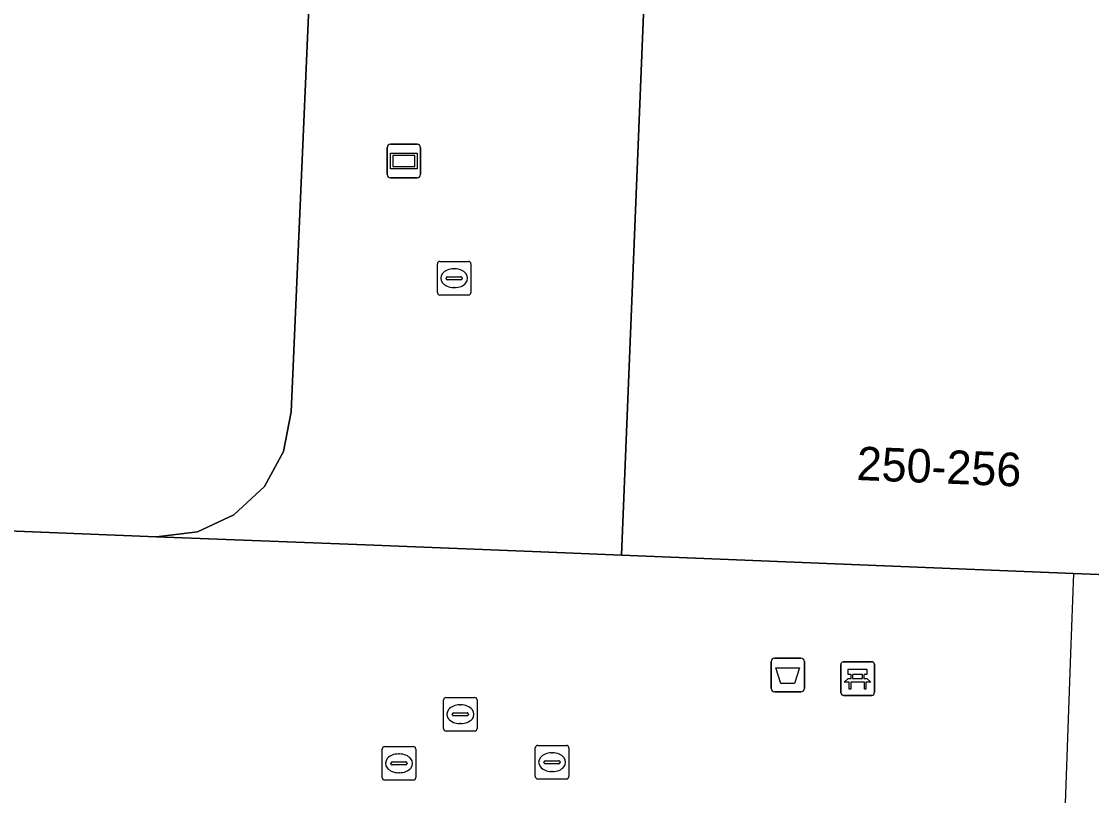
# Model space of a CAD drawing. Extents: x 160888 to 161385, y 386490 to 386908.
# Drawn here: x 161173.3 to 161205.21, y 386561.84 to 386584.91 of the extents above; entities that cross this region are included whole.
import ezdxf

# ---------------------------------------------------------------- set-up
doc = ezdxf.new("R2010")
doc.units = 0
for name, color, linetype in [('IMGEO_Afvalbak', 7, 'Continuous'), ('IMGEO_Bank', 7, 'Continuous'), ('IMGEO_Hek', 7, 'Continuous'), ('IMGEO_Kolk', 7, 'Continuous'), ('IMGEO_Pand', 7, 'Continuous'), ('IMGEO_Pand_nummerreeks', 7, 'Continuous'), ('IMGEO_Reclamebord', 7, 'Continuous'), ('IMGEO_Rioolput', 7, 'Continuous'), ('IMGEO_Voetgangersgebied_open', 7, 'Continuous')]:
    doc.layers.add(name, color=color, linetype=linetype)

msp = doc.modelspace()

# ---------------------------------------------------------------- linework, layer by layer
at = {"layer": 'IMGEO_Afvalbak'}
for p, q in [((161195.655, 386565.033), (161195.655, 386565.833)), ((161195.655, 386565.833), (161195.655, 386565.033)), ((161195.755, 386565.933), (161196.545, 386565.933)), ((161196.545, 386565.933), (161195.755, 386565.933)), ((161196.645, 386565.833), (161196.645, 386565.033)), ((161196.645, 386565.033), (161196.645, 386565.833)), ((161196.545, 386564.933), (161195.755, 386564.933)), ((161195.755, 386564.933), (161196.545, 386564.933))]:
    msp.add_line(p, q, dxfattribs=at)
msp.add_lwpolyline([(161195.798, 386565.647), (161196.502, 386565.647), (161196.353, 386565.177), (161195.947, 386565.177), (161195.798, 386565.647)], dxfattribs=at)
for centre, start, end in [((161195.755, 386565.833), 90, 180), ((161195.755, 386565.833), 90, 180), ((161196.545, 386565.833), 0, 90), ((161196.545, 386565.833), 360, 90), ((161195.755, 386565.033), 180, 270), ((161195.755, 386565.033), 180, 270), ((161196.545, 386565.033), 270, 0), ((161196.545, 386565.033), 270, 0)]:
    msp.add_arc(centre, 0.1, start, end, dxfattribs=at)
at = {"layer": 'IMGEO_Bank'}
for p, q in [((161197.732, 386564.9), (161197.732, 386565.741)), ((161197.732, 386565.741), (161197.732, 386564.9)), ((161197.807, 386565.825), (161198.648, 386565.825)), ((161198.648, 386565.825), (161197.807, 386565.825)), ((161198.732, 386565.75), (161198.732, 386564.909)), ((161198.732, 386564.909), (161198.732, 386565.75)), ((161198.041, 386565.331), (161198.041, 386565.437)), ((161198.085, 386565.437), (161198.085, 386565.331)), ((161198.373, 386565.443), (161198.091, 386565.443)), ((161198.091, 386565.325), (161198.373, 386565.325)), ((161198.379, 386565.331), (161198.379, 386565.437)), ((161198.423, 386565.437), (161198.423, 386565.331)), ((161198.429, 386565.223), (161198.036, 386565.223)), ((161198.657, 386564.825), (161197.816, 386564.825)), ((161197.816, 386564.825), (161198.657, 386564.825))]:
    msp.add_line(p, q, dxfattribs=at)
for points in [[(161197.979, 386565.223), (161197.837, 386565.223), (161197.949, 386565.325), (161198.035, 386565.325)], [(161198.035, 386565.443), (161197.949, 386565.443), (161197.949, 386565.604), (161198.512, 386565.604), (161198.512, 386565.443), (161198.429, 386565.443)], [(161198.429, 386565.325), (161198.512, 386565.325), (161198.624, 386565.223), (161198.485, 386565.223)], [(161198.029, 386565.216), (161198.029, 386565.009), (161197.986, 386565.009), (161197.986, 386565.216)], [(161198.479, 386565.216), (161198.479, 386565.009), (161198.435, 386565.009), (161198.435, 386565.216)]]:
    msp.add_lwpolyline(points, dxfattribs=at)
for centre, radius, start, end in [((161197.81, 386565.747), 0.0779, 92.4484, 184.2845), ((161197.81, 386565.747), 0.0779, 92.4484, 184.2845), ((161198.654, 386565.747), 0.0779, 2.4484, 94.2845), ((161198.654, 386565.747), 0.0779, 2.4484, 94.2845), ((161198.034, 386565.436), 0.00671, 2.8957, 87.1043), ((161198.034, 386565.332), 0.00671, 272.8957, 357.1043), ((161198.091, 386565.436), 0.00671, 92.8957, 177.1043), ((161198.091, 386565.332), 0.00671, 182.8957, 267.1043), ((161198.373, 386565.436), 0.00671, 2.8957, 87.1043), ((161198.373, 386565.332), 0.00671, 272.8957, 357.1043), ((161198.43, 386565.436), 0.00671, 92.8957, 177.1043), ((161198.43, 386565.332), 0.00671, 182.8957, 267.1043), ((161197.979, 386565.216), 0.00671, 2.8957, 87.1043), ((161198.036, 386565.216), 0.00671, 92.8957, 177.1043), ((161198.428, 386565.216), 0.00671, 2.8957, 87.1043), ((161198.485, 386565.216), 0.00671, 92.8957, 177.1043), ((161197.81, 386564.903), 0.0779, 182.4484, 274.2845), ((161197.81, 386564.903), 0.0779, 182.4484, 274.2845), ((161198.654, 386564.903), 0.0779, 272.4484, 4.2845), ((161198.654, 386564.903), 0.0779, 272.4484, 4.2845)]:
    msp.add_arc(centre, radius, start, end, dxfattribs=at)
at = {"layer": 'IMGEO_Hek'}
for points in [[(161204.671, 386568.461), (161204.584, 386566.069)], [(161204.584, 386566.069), (161204.309, 386558.529)]]:
    msp.add_lwpolyline(points, dxfattribs=at)
at = {"layer": 'IMGEO_Kolk'}
for p, q in [((161185.705, 386576.832), (161185.705, 386577.684)), ((161185.78, 386577.758), (161186.632, 386577.758)), ((161186.193, 386577.538), (161186.218, 386577.538)), ((161186.706, 386577.684), (161186.706, 386576.832)), ((161185.964, 386577.252), (161185.964, 386577.264)), ((161186.402, 386577.215), (161186.004, 386577.215)), ((161186.007, 386577.301), (161186.405, 386577.301)), ((161186.448, 386577.264), (161186.448, 386577.252)), ((161186.216, 386576.978), (161186.191, 386576.978)), ((161186.632, 386576.758), (161185.78, 386576.758)), ((161188.623, 386562.406), (161188.623, 386563.258)), ((161188.698, 386563.332), (161189.55, 386563.332)), ((161189.111, 386563.112), (161189.136, 386563.112)), ((161189.624, 386563.258), (161189.624, 386562.406)), ((161188.882, 386562.826), (161188.882, 386562.838)), ((161189.32, 386562.789), (161188.922, 386562.789)), ((161188.925, 386562.875), (161189.323, 386562.875)), ((161189.366, 386562.838), (161189.366, 386562.826)), ((161189.134, 386562.552), (161189.109, 386562.552)), ((161189.55, 386562.332), (161188.698, 386562.332))]:
    msp.add_line(p, q, dxfattribs=at)
for points in [[(161185.705, 386576.832), (161185.705, 386577.684)], [(161185.78, 386577.758), (161186.632, 386577.758)], [(161186.706, 386577.684), (161186.706, 386576.832)], [(161186.632, 386576.758), (161185.78, 386576.758)], [(161188.623, 386562.406), (161188.623, 386563.258)], [(161188.698, 386563.332), (161189.55, 386563.332)], [(161189.624, 386563.258), (161189.624, 386562.406)], [(161189.55, 386562.332), (161188.698, 386562.332)]]:
    msp.add_lwpolyline(points, dxfattribs=at)
for centre, radius, start, end in [((161185.782, 386577.682), 0.0765, 91.552, 178.448), ((161185.782, 386577.682), 0.0765, 91.552, 178.448), ((161186.63, 386577.682), 0.0765, 1.552, 88.448), ((161186.63, 386577.682), 0.0765, 1.552, 88.448), ((161186.004, 386577.261), 0.0403, 85.8775, 175.7526), ((161186.001, 386577.251), 0.0366, 178.938, 274.7102), ((161186.405, 386577.258), 0.043, 264.8664, 352.4533), ((161186.409, 386577.263), 0.0386, 1.7309, 96.639), ((161185.782, 386576.834), 0.0765, 181.552, 268.448), ((161185.782, 386576.834), 0.0765, 181.552, 268.448), ((161186.63, 386576.834), 0.0765, 271.552, 358.448), ((161186.63, 386576.834), 0.0765, 271.552, 358.448), ((161188.7, 386563.256), 0.0765, 91.552, 178.448), ((161188.7, 386563.256), 0.0765, 91.552, 178.448), ((161189.548, 386563.256), 0.0765, 1.552, 88.448), ((161189.548, 386563.256), 0.0765, 1.552, 88.448), ((161188.922, 386562.835), 0.0403, 85.8775, 175.7526), ((161188.919, 386562.825), 0.0366, 178.938, 274.7102), ((161189.323, 386562.832), 0.043, 264.8664, 352.4533), ((161189.327, 386562.837), 0.0386, 1.7309, 96.639), ((161188.7, 386562.408), 0.0765, 181.552, 268.448), ((161188.7, 386562.408), 0.0765, 181.552, 268.448), ((161189.548, 386562.408), 0.0765, 271.552, 358.448), ((161189.548, 386562.408), 0.0765, 271.552, 358.448)]:
    msp.add_arc(centre, radius, start, end, dxfattribs=at)
for centre, major_axis, ratio, start_param, end_param in [((161186.192, 386577.258), (-0.387, 0.002), 0.722429, 4.712389, 7.853982), ((161186.217, 386577.258), (-0.39, 0.002), 0.717154, 1.570796, 4.712389), ((161189.11, 386562.832), (-0.387, 0.002), 0.722429, 4.712389, 7.853982), ((161189.135, 386562.832), (-0.39, 0.002), 0.717154, 1.570796, 4.712389)]:
    msp.add_ellipse(centre, major_axis=major_axis, ratio=ratio, start_param=start_param, end_param=end_param, dxfattribs=at)
at = {"layer": 'IMGEO_Pand'}
msp.add_lwpolyline([(161144.239, 386630.361), (161141.97, 386574.785), (161142.127, 386573.608), (161142.623, 386572.549), (161143.412, 386571.685), (161144.419, 386571.089), (161145.572, 386570.831), (161177.328, 386569.555), (161178.554, 386569.701), (161179.639, 386570.209), (161180.548, 386571.054), (161181.119, 386572.09), (161181.347, 386573.278), (161182.646, 386603.083)], dxfattribs=at)
msp.add_lwpolyline([(161191.198, 386569.006), (161204.671, 386568.461), (161212.673, 386568.138), (161213.252, 386579.772), (161213.556, 386587.296), (161214.141, 386601.806), (161192.456, 386602.678), (161192.441, 386602.269), (161192.541, 386602.265)], close=True, dxfattribs=at)
at = {"layer": 'IMGEO_Reclamebord'}
for p, q in [((161184.209, 386580.351), (161184.209, 386581.151)), ((161184.209, 386581.151), (161184.209, 386580.351)), ((161184.309, 386581.251), (161185.099, 386581.251)), ((161185.099, 386581.251), (161184.309, 386581.251)), ((161185.199, 386581.151), (161185.199, 386580.351)), ((161185.199, 386580.351), (161185.199, 386581.151)), ((161185.099, 386580.251), (161184.309, 386580.251)), ((161184.309, 386580.251), (161185.099, 386580.251))]:
    msp.add_line(p, q, dxfattribs=at)
for points in [[(161184.31, 386580.983), (161185.098, 386580.983), (161185.098, 386580.519), (161184.31, 386580.519), (161184.31, 386580.983)], [(161184.375, 386580.918), (161184.375, 386580.584), (161185.033, 386580.584), (161185.033, 386580.918), (161184.375, 386580.918)]]:
    msp.add_lwpolyline(points, dxfattribs=at)
for centre, start, end in [((161184.309, 386581.151), 90, 180), ((161184.309, 386581.151), 90, 180), ((161185.099, 386581.151), 0, 90), ((161185.099, 386581.151), 360, 90), ((161184.309, 386580.351), 180, 270), ((161184.309, 386580.351), 180, 270), ((161185.099, 386580.351), 270, 0), ((161185.099, 386580.351), 270, 0)]:
    msp.add_arc(centre, 0.1, start, end, dxfattribs=at)
at = {"layer": 'IMGEO_Rioolput'}
for p, q in [((161185.888, 386563.836), (161185.888, 386564.688)), ((161185.963, 386564.762), (161186.815, 386564.762)), ((161186.889, 386564.688), (161186.889, 386563.836)), ((161186.376, 386564.542), (161186.401, 386564.542)), ((161186.147, 386564.256), (161186.147, 386564.268)), ((161186.585, 386564.219), (161186.187, 386564.219)), ((161186.19, 386564.305), (161186.588, 386564.305)), ((161186.631, 386564.268), (161186.631, 386564.256)), ((161186.815, 386563.762), (161185.963, 386563.762)), ((161186.399, 386563.982), (161186.374, 386563.982)), ((161184.059, 386562.373), (161184.059, 386563.225)), ((161184.134, 386563.299), (161184.986, 386563.299)), ((161185.06, 386563.225), (161185.06, 386562.373)), ((161184.318, 386562.793), (161184.318, 386562.805)), ((161184.361, 386562.842), (161184.759, 386562.842)), ((161184.547, 386563.079), (161184.572, 386563.079)), ((161184.802, 386562.805), (161184.802, 386562.793)), ((161184.756, 386562.756), (161184.358, 386562.756)), ((161184.57, 386562.519), (161184.545, 386562.519)), ((161184.986, 386562.299), (161184.134, 386562.299))]:
    msp.add_line(p, q, dxfattribs=at)
for points in [[(161185.888, 386563.836), (161185.888, 386564.688)], [(161185.963, 386564.762), (161186.815, 386564.762)], [(161186.889, 386564.688), (161186.889, 386563.836)], [(161186.815, 386563.762), (161185.963, 386563.762)], [(161184.059, 386562.373), (161184.059, 386563.225)], [(161184.134, 386563.299), (161184.986, 386563.299)], [(161185.06, 386563.225), (161185.06, 386562.373)], [(161184.986, 386562.299), (161184.134, 386562.299)]]:
    msp.add_lwpolyline(points, dxfattribs=at)
for centre, radius, start, end in [((161185.965, 386564.686), 0.0765, 91.552, 178.448), ((161185.965, 386564.686), 0.0765, 91.552, 178.448), ((161186.813, 386564.686), 0.0765, 1.552, 88.448), ((161186.813, 386564.686), 0.0765, 1.552, 88.448), ((161186.187, 386564.265), 0.0403, 85.8775, 175.7526), ((161186.184, 386564.255), 0.0366, 178.938, 274.7102), ((161186.588, 386564.262), 0.043, 264.8664, 352.4533), ((161186.592, 386564.267), 0.0386, 1.7309, 96.639), ((161185.965, 386563.838), 0.0765, 181.552, 268.448), ((161185.965, 386563.838), 0.0765, 181.552, 268.448), ((161186.813, 386563.838), 0.0765, 271.552, 358.448), ((161186.813, 386563.838), 0.0765, 271.552, 358.448), ((161184.136, 386563.223), 0.0765, 91.552, 178.448), ((161184.136, 386563.223), 0.0765, 91.552, 178.448), ((161184.984, 386563.223), 0.0765, 1.552, 88.448), ((161184.984, 386563.223), 0.0765, 1.552, 88.448), ((161184.358, 386562.802), 0.0403, 85.8775, 175.7526), ((161184.355, 386562.792), 0.0366, 178.938, 274.7102), ((161184.759, 386562.799), 0.043, 264.8664, 352.4533), ((161184.763, 386562.804), 0.0386, 1.7309, 96.639), ((161184.136, 386562.375), 0.0765, 181.552, 268.448), ((161184.136, 386562.375), 0.0765, 181.552, 268.448), ((161184.984, 386562.375), 0.0765, 271.552, 358.448), ((161184.984, 386562.375), 0.0765, 271.552, 358.448)]:
    msp.add_arc(centre, radius, start, end, dxfattribs=at)
for centre, major_axis, ratio, start_param, end_param in [((161186.375, 386564.262), (-0.387, 0.002), 0.722429, 4.712389, 7.853982), ((161186.4, 386564.262), (-0.39, 0.002), 0.717154, 1.570796, 4.712389), ((161184.546, 386562.799), (-0.387, 0.002), 0.722429, 4.712389, 7.853982), ((161184.571, 386562.799), (-0.39, 0.002), 0.717154, 1.570796, 4.712389)]:
    msp.add_ellipse(centre, major_axis=major_axis, ratio=ratio, start_param=start_param, end_param=end_param, dxfattribs=at)
at = {"layer": 'IMGEO_Voetgangersgebied_open'}
for points in [[(161182.646, 386603.083), (161181.347, 386573.278), (161181.119, 386572.09), (161180.548, 386571.054), (161179.639, 386570.209), (161178.554, 386569.701), (161177.328, 386569.555), (161183.563, 386569.308), (161188.786, 386569.101), (161191.198, 386569.006), (161192.541, 386602.265)], [(161213.556, 386587.296), (161213.252, 386579.772), (161212.673, 386568.138), (161204.671, 386568.461), (161191.198, 386569.006), (161188.786, 386569.101), (161183.563, 386569.308), (161177.328, 386569.555), (161145.572, 386570.831), (161144.419, 386571.089), (161143.412, 386571.685), (161139.877, 386568.704)]]:
    msp.add_lwpolyline(points, dxfattribs=at)

# ---------------------------------------------------------------- texts
at = {"layer": 'IMGEO_Pand_nummerreeks'}
msp.add_text('250-256', height=1, rotation=357.6854, dxfattribs=at).set_placement((161198.191, 386571.245))

doc.saveas('drawing.dxf')
